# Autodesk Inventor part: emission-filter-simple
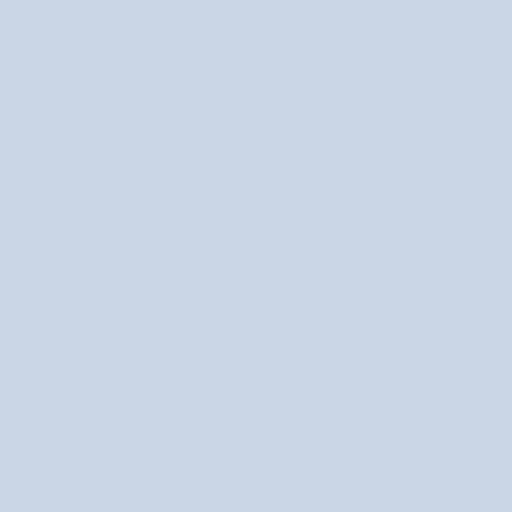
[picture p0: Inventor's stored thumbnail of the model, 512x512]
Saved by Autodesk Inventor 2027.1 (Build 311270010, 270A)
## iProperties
Created: 2026-08
Part Number: emission-filter-simple
Material: Generic
Document SubType Name: Modeling
Designer: dunge
Density: 1 g/cm^3
Appearance: Default
Author: dunge
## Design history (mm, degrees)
sketch "Sketch1"
  geometry: C1 r 12.7 at (0, 0); C2 r 13.335 at (0, 0); 1 further point
  constraints: 2 centre point, 2 coincident
  dimensions: "d0" = 25.4 diameter of C1; "d1" = 0.635 radial gap between concentric circles of C2 C1
extrude "Extrusion1" new body sketch "Sketch1" stored distance "d2" = 1.27; taper "d3" = 0 deg
extrude "Extrusion2" join sketch "Sketch1" stored distance "d4" = 1.905; taper "d5" = 0 deg
body "Solid1"
node "Finishes"
node "Finish1" dims "Finish1_Area" = 101.3415
node "Finish2" dims "Finish2_Area" = 31.41586
